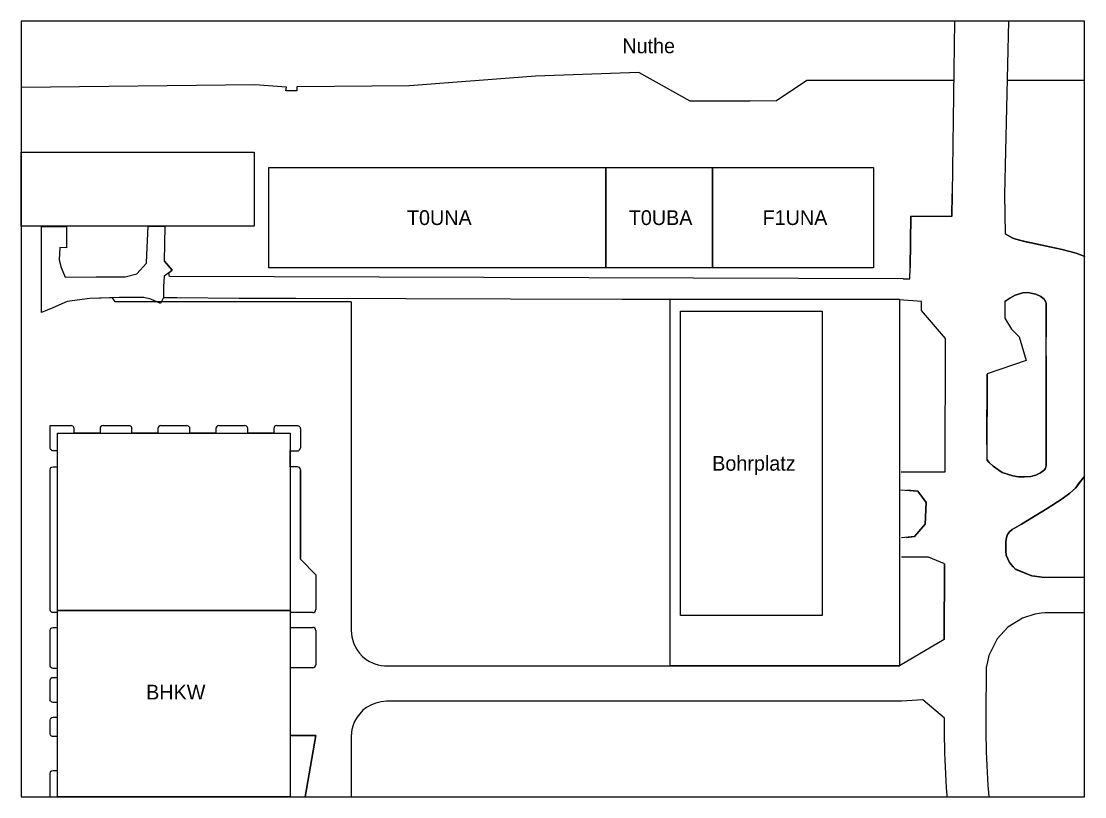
# Model space of a CAD drawing. Extents: x 0 to 0.18, y 0 to 0.131.
import ezdxf

# ---------------------------------------------------------------- set-up
doc = ezdxf.new("R2010")
doc.units = 0
doc.layers.add('ECN_KOPF_DE', color=7, linetype='Continuous')

msp = doc.modelspace()

# ---------------------------------------------------------------- linework, layer by layer
at = {"layer": 'ECN_KOPF_DE'}
for p, q in [((0.17999, 0.13127), (0, 0.13127)), ((0, 0.13127), (0, 0)), ((0.15796, 0.13127), (0.15756, 0.10208)), ((0.16711, 0.13127), (0.16643, 0.10192)), ((0.17999, 0), (0.17999, 0.13127)), ((0.10453, 0.12259), (0.08702, 0.122)), ((0.11323, 0.11773), (0.10453, 0.12259)), ((0.08702, 0.122), (0.06569, 0.12035)), ((0.13296, 0.12123), (0.12783, 0.11779)), ((0.15782, 0.12124), (0.13296, 0.12123)), ((0.17999, 0.12125), (0.16688, 0.12124)), ((0.03953, 0.12054), (0, 0.12008)), ((0.04489, 0.12013), (0.03953, 0.12054)), ((0.04476, 0.11949), (0.04489, 0.12013)), ((0.04666, 0.11947), (0.04476, 0.11949)), ((0.04667, 0.12015), (0.04666, 0.11947)), ((0.06569, 0.12035), (0.04667, 0.12015)), ((0.1234, 0.11777), (0.11323, 0.11773)), ((0.12783, 0.11779), (0.1234, 0.11777)), ((0, 0.10914), (0.03941, 0.10914)), ((0, 0.09658), (0, 0.10914)), ((0.03941, 0.10914), (0.03941, 0.09658)), ((0.04193, 0.10651), (0.09893, 0.10651)), ((0.04193, 0.08954), (0.04193, 0.10651)), ((0.09893, 0.10651), (0.09893, 0.08954)), ((0.09893, 0.10651), (0.11703, 0.10651)), ((0.09893, 0.08954), (0.09893, 0.10651)), ((0.11703, 0.10651), (0.11703, 0.08954)), ((0.11703, 0.10651), (0.14423, 0.10651)), ((0.11703, 0.08954), (0.11703, 0.10651)), ((0.14423, 0.10651), (0.14423, 0.08954)), ((0.15751, 0.0982), (0.15756, 0.10208)), ((0.15756, 0.10208), (0.15751, 0.0982)), ((0.16643, 0.10192), (0.16654, 0.09529)), ((0.16643, 0.10192), (0.16654, 0.09529)), ((0.15048, 0.08954), (0.15059, 0.09828)), ((0.15059, 0.09828), (0.15048, 0.08954)), ((0.15059, 0.09828), (0.15751, 0.0982)), ((0.15751, 0.0982), (0.15059, 0.09828)), ((0.03941, 0.09658), (0, 0.09658)), ((0.00342, 0.09654), (0.00763, 0.09655)), ((0.00342, 0.09654), (0.00763, 0.09655)), ((0.00342, 0.09296), (0.00342, 0.09654)), ((0.00342, 0.09296), (0.00342, 0.09654)), ((0.00763, 0.09655), (0.00764, 0.0929)), ((0.00763, 0.09655), (0.00764, 0.0929)), ((0.02127, 0.09172), (0.02147, 0.09656)), ((0.02127, 0.09172), (0.02147, 0.09656)), ((0.02147, 0.09656), (0.02438, 0.09656)), ((0.02147, 0.09656), (0.02438, 0.09656)), ((0.02422, 0.09064), (0.02438, 0.09658)), ((0.02422, 0.09064), (0.02438, 0.09658)), ((0.16654, 0.09529), (0.16782, 0.09455)), ((0.16782, 0.09455), (0.16654, 0.09529)), ((0.16782, 0.09455), (0.16835, 0.09437)), ((0.16835, 0.09437), (0.16782, 0.09455)), ((0.16835, 0.09437), (0.16984, 0.094)), ((0.16943, 0.09409), (0.16835, 0.09437)), ((0.17619, 0.09262), (0.16943, 0.09409)), ((0.16984, 0.094), (0.17619, 0.09262)), ((0.00342, 0.08895), (0.00342, 0.09296)), ((0.00342, 0.08895), (0.00342, 0.09296)), ((0.00653, 0.09296), (0.0064, 0.09087)), ((0.00653, 0.09296), (0.0064, 0.09087)), ((0.00764, 0.0929), (0.00653, 0.09296)), ((0.00764, 0.0929), (0.00653, 0.09296)), ((0.17619, 0.09262), (0.17857, 0.09203)), ((0.17857, 0.09203), (0.17619, 0.09262)), ((0.17857, 0.09203), (0.18001, 0.09148)), ((0.18001, 0.09148), (0.17857, 0.09203)), ((0.0064, 0.09087), (0.00676, 0.08958)), ((0.0064, 0.09087), (0.00676, 0.08958)), ((0.01954, 0.0885), (0.02121, 0.09031)), ((0.01954, 0.0885), (0.02121, 0.09031)), ((0.02121, 0.09031), (0.02127, 0.09172)), ((0.02121, 0.09031), (0.02127, 0.09172)), ((0.02553, 0.08916), (0.02422, 0.09064)), ((0.02422, 0.09064), (0.02553, 0.08916)), ((0.02553, 0.08916), (0.02422, 0.09064)), ((0.02422, 0.09064), (0.02553, 0.08916)), ((0.00343, 0.08383), (0.00342, 0.08895)), ((0.00343, 0.08383), (0.00342, 0.08895)), ((0.00676, 0.08958), (0.00744, 0.08796)), ((0.00676, 0.08958), (0.00744, 0.08796)), ((0.01758, 0.088), (0.01954, 0.0885)), ((0.01758, 0.088), (0.01954, 0.0885)), ((0.025, 0.0887), (0.02416, 0.08815)), ((0.025, 0.0887), (0.02416, 0.08815)), ((0.025, 0.0887), (0.02416, 0.08815)), ((0.025, 0.0887), (0.02553, 0.08916)), ((0.02553, 0.08916), (0.025, 0.0887)), ((0.025, 0.0887), (0.02553, 0.08916)), ((0.02553, 0.08916), (0.025, 0.0887)), ((0.0251, 0.08805), (0.025, 0.0887)), ((0.0251, 0.08805), (0.025, 0.0887)), ((0.0251, 0.08805), (0.025, 0.0887)), ((0.09893, 0.08954), (0.04193, 0.08954)), ((0.11703, 0.08954), (0.09893, 0.08954)), ((0.14423, 0.08954), (0.11703, 0.08954)), ((0.15043, 0.08765), (0.15048, 0.08954)), ((0.00744, 0.08796), (0.01265, 0.08799)), ((0.00744, 0.08796), (0.01265, 0.08799)), ((0.01265, 0.08799), (0.01758, 0.088)), ((0.01265, 0.08799), (0.01758, 0.088)), ((0.0241, 0.0864), (0.02408, 0.08452)), ((0.0241, 0.0864), (0.02408, 0.08452)), ((0.0241, 0.0864), (0.02408, 0.08452)), ((0.02416, 0.08815), (0.0241, 0.0864)), ((0.02416, 0.08815), (0.0241, 0.0864)), ((0.02416, 0.08815), (0.0241, 0.0864)), ((0.14928, 0.08767), (0.0251, 0.08805)), ((0.14928, 0.08767), (0.15043, 0.08765)), ((0.16824, 0.08489), (0.16734, 0.0844)), ((0.16734, 0.0844), (0.16824, 0.08489)), ((0.16951, 0.08531), (0.16824, 0.08489)), ((0.16824, 0.08489), (0.16882, 0.0851)), ((0.16882, 0.0851), (0.16951, 0.08531)), ((0.17037, 0.08536), (0.16951, 0.08531)), ((0.16951, 0.08531), (0.17037, 0.08536)), ((0.17171, 0.08507), (0.17037, 0.08536)), ((0.17037, 0.08536), (0.17171, 0.08507)), ((0.1726, 0.08467), (0.17171, 0.08507)), ((0.17171, 0.08507), (0.1726, 0.08467)), ((0.17318, 0.08416), (0.1726, 0.08467)), ((0.1726, 0.08467), (0.17318, 0.08416)), ((0.00342, 0.08198), (0.00343, 0.08383)), ((0.00342, 0.08198), (0.00343, 0.08383)), ((0.00777, 0.08382), (0.00532, 0.08279)), ((0.00777, 0.08382), (0.00532, 0.08279)), ((0.01162, 0.08433), (0.00777, 0.08382)), ((0.01162, 0.08433), (0.00777, 0.08382)), ((0.01162, 0.08433), (0.00777, 0.08382)), ((0.01656, 0.08449), (0.01162, 0.08433)), ((0.01656, 0.08449), (0.01162, 0.08433)), ((0.01542, 0.08445), (0.01162, 0.08433)), ((0.01592, 0.08377), (0.01542, 0.08445)), ((0.05534, 0.08377), (0.01592, 0.08377)), ((0.02077, 0.0845), (0.01656, 0.08449)), ((0.02077, 0.0845), (0.01656, 0.08449)), ((0.02191, 0.08422), (0.02077, 0.0845)), ((0.02191, 0.08422), (0.02077, 0.0845)), ((0.02355, 0.08348), (0.02191, 0.08422)), ((0.02355, 0.08348), (0.02191, 0.08422)), ((0.02408, 0.08452), (0.02355, 0.08348)), ((0.02408, 0.08452), (0.02355, 0.08348)), ((0.02408, 0.08452), (0.02633, 0.08449)), ((0.02633, 0.08449), (0.03689, 0.08442)), ((0.03689, 0.08442), (0.04649, 0.0844)), ((0.04649, 0.0844), (0.06511, 0.08434)), ((0.05584, 0.08377), (0.05534, 0.08377)), ((0.05584, 0.08377), (0.05584, 0.02815)), ((0.06511, 0.08434), (0.0828, 0.08429)), ((0.0828, 0.08429), (0.10173, 0.08423)), ((0.10173, 0.08423), (0.11909, 0.08421)), ((0.15236, 0.08383), (0.14865, 0.0841)), ((0.15237, 0.08232), (0.15236, 0.08383)), ((0.15237, 0.08232), (0.15236, 0.08383)), ((0.15236, 0.08383), (0.15236, 0.08383)), ((0.16649, 0.08382), (0.16648, 0.08102)), ((0.16649, 0.08382), (0.16648, 0.08102)), ((0.16734, 0.0844), (0.16649, 0.08382)), ((0.16649, 0.08382), (0.16734, 0.0844)), ((0.17349, 0.08357), (0.17318, 0.08416)), ((0.17318, 0.08416), (0.17349, 0.08357)), ((0.17348, 0.08005), (0.17349, 0.08357)), ((0.17349, 0.08357), (0.17348, 0.08005)), ((0.00532, 0.08279), (0.00342, 0.08198)), ((0.00532, 0.08279), (0.00342, 0.08198)), ((0.11156, 0.08221), (0.13556, 0.08221)), ((0.11156, 0.03068), (0.11156, 0.08221)), ((0.13556, 0.08221), (0.13556, 0.03068)), ((0.15642, 0.07757), (0.15237, 0.08232)), ((0.15642, 0.07757), (0.15237, 0.08232)), ((0.16648, 0.08102), (0.16764, 0.07914)), ((0.16648, 0.08102), (0.16764, 0.07914)), ((0.17348, 0.08005), (0.17344, 0.07556)), ((0.17346, 0.07387), (0.17348, 0.08005)), ((0.15636, 0.05502), (0.15642, 0.07757)), ((0.15636, 0.05502), (0.15642, 0.07757)), ((0.16764, 0.07914), (0.1689, 0.07783)), ((0.16764, 0.07914), (0.1689, 0.07783)), ((0.1689, 0.07783), (0.17011, 0.07386)), ((0.1689, 0.07783), (0.17011, 0.07386)), ((0.17011, 0.07386), (0.16348, 0.07158)), ((0.17011, 0.07386), (0.16349, 0.07158)), ((0.17344, 0.07556), (0.17346, 0.07387)), ((0.17348, 0.06465), (0.17346, 0.07387)), ((0.17346, 0.07387), (0.17348, 0.06465)), ((0.16348, 0.07158), (0.16342, 0.05711)), ((0.16343, 0.05965), (0.16348, 0.07156)), ((0.17348, 0.05605), (0.17348, 0.06465)), ((0.17348, 0.06465), (0.17348, 0.0577)), ((0.00489, 0.05905), (0.00489, 0.06284)), ((0.00489, 0.06284), (0.00844, 0.06282)), ((0.00614, 0.06157), (0.04554, 0.06157)), ((0.00614, 0.03152), (0.00614, 0.06157)), ((0.0087, 0.06275), (0.00844, 0.06282)), ((0.00884, 0.06261), (0.0087, 0.06275)), ((0.00891, 0.06248), (0.00884, 0.06261)), ((0.00894, 0.06232), (0.00891, 0.06248)), ((0.00894, 0.06157), (0.00894, 0.06232)), ((0.01334, 0.06157), (0.00894, 0.06157)), ((0.01338, 0.06252), (0.01334, 0.06232)), ((0.01334, 0.06232), (0.01334, 0.06157)), ((0.01348, 0.06267), (0.01338, 0.06252)), ((0.01363, 0.06277), (0.01348, 0.06267)), ((0.01384, 0.06282), (0.01363, 0.06277)), ((0.01384, 0.06282), (0.01824, 0.06282)), ((0.0185, 0.06275), (0.01824, 0.06282)), ((0.01864, 0.06261), (0.0185, 0.06275)), ((0.01871, 0.06248), (0.01864, 0.06261)), ((0.01874, 0.06232), (0.01871, 0.06248)), ((0.01874, 0.06157), (0.01874, 0.06232)), ((0.02314, 0.06157), (0.01874, 0.06157)), ((0.02318, 0.06252), (0.02314, 0.06232)), ((0.02314, 0.06232), (0.02314, 0.06157)), ((0.02328, 0.06267), (0.02318, 0.06252)), ((0.02343, 0.06277), (0.02328, 0.06267)), ((0.02364, 0.06282), (0.02343, 0.06277)), ((0.02364, 0.06282), (0.02804, 0.06282)), ((0.0283, 0.06275), (0.02804, 0.06282)), ((0.02844, 0.06261), (0.0283, 0.06275)), ((0.02851, 0.06248), (0.02844, 0.06261)), ((0.02854, 0.06232), (0.02851, 0.06248)), ((0.02854, 0.06157), (0.02854, 0.06232)), ((0.03294, 0.06157), (0.02854, 0.06157)), ((0.03298, 0.06252), (0.03294, 0.06232)), ((0.03294, 0.06232), (0.03294, 0.06157)), ((0.03308, 0.06267), (0.03298, 0.06252)), ((0.03323, 0.06277), (0.03308, 0.06267)), ((0.03344, 0.06282), (0.03323, 0.06277)), ((0.03344, 0.06282), (0.03784, 0.06282)), ((0.0381, 0.06275), (0.03784, 0.06282)), ((0.03824, 0.06261), (0.0381, 0.06275)), ((0.03831, 0.06248), (0.03824, 0.06261)), ((0.03834, 0.06232), (0.03831, 0.06248)), ((0.03834, 0.06157), (0.03834, 0.06232)), ((0.04274, 0.06157), (0.03834, 0.06157)), ((0.04278, 0.06252), (0.04274, 0.06232)), ((0.04274, 0.06232), (0.04274, 0.06157)), ((0.04288, 0.06267), (0.04278, 0.06252)), ((0.04303, 0.06277), (0.04288, 0.06267)), ((0.04324, 0.06282), (0.04303, 0.06277)), ((0.04324, 0.06282), (0.04676, 0.06282)), ((0.04554, 0.06157), (0.04554, 0.03152)), ((0.04674, 0.06282), (0.04679, 0.06281)), ((0.04679, 0.06281), (0.04685, 0.0628)), ((0.04685, 0.0628), (0.04693, 0.06278)), ((0.04693, 0.06278), (0.04702, 0.06273)), ((0.04702, 0.06273), (0.04709, 0.06267)), ((0.04709, 0.06267), (0.04716, 0.06259)), ((0.04716, 0.06259), (0.0472, 0.0625)), ((0.0472, 0.0625), (0.04723, 0.06242)), ((0.04723, 0.06242), (0.04724, 0.06232)), ((0.04724, 0.06232), (0.04724, 0.05905)), ((0.00496, 0.05879), (0.00489, 0.05905)), ((0.00509, 0.05865), (0.00496, 0.05879)), ((0.00522, 0.05858), (0.00509, 0.05865)), ((0.00539, 0.05855), (0.00522, 0.05858)), ((0.00614, 0.05855), (0.00539, 0.05855)), ((0.00614, 0.05585), (0.00614, 0.05855)), ((0.04554, 0.05585), (0.04554, 0.05855)), ((0.04554, 0.05855), (0.04674, 0.05855)), ((0.04674, 0.05855), (0.0469, 0.05858)), ((0.0469, 0.05858), (0.04703, 0.05865)), ((0.04703, 0.05865), (0.04717, 0.05879)), ((0.04717, 0.05879), (0.04724, 0.05905)), ((0.17348, 0.0577), (0.17348, 0.05605)), ((0.00503, 0.05571), (0.00518, 0.05581)), ((0.00518, 0.05581), (0.00539, 0.05585)), ((0.00539, 0.05585), (0.00614, 0.05585)), ((0.04674, 0.05585), (0.04554, 0.05585)), ((0.04694, 0.05581), (0.04674, 0.05585)), ((0.04709, 0.05571), (0.04694, 0.05581)), ((0.16342, 0.05711), (0.16382, 0.05658)), ((0.16382, 0.05658), (0.16346, 0.05705)), ((0.16382, 0.05658), (0.1645, 0.05597)), ((0.1645, 0.05597), (0.16382, 0.05658)), ((0.1645, 0.05597), (0.16604, 0.05491)), ((0.16529, 0.05538), (0.1645, 0.05597)), ((0.17337, 0.05561), (0.17348, 0.05605)), ((0.17348, 0.05605), (0.17337, 0.05561)), ((0.00489, 0.05535), (0.00493, 0.05556)), ((0.00489, 0.03167), (0.00489, 0.05535)), ((0.00493, 0.05556), (0.00503, 0.05571)), ((0.04719, 0.05556), (0.04709, 0.05571)), ((0.04724, 0.05535), (0.04719, 0.05556)), ((0.04724, 0.05535), (0.04724, 0.04035)), ((0.04724, 0.04022), (0.04724, 0.05522)), ((0.14896, 0.05498), (0.15636, 0.05502)), ((0.14987, 0.05499), (0.15636, 0.05502)), ((0.16604, 0.05491), (0.16529, 0.05538)), ((0.16604, 0.05491), (0.16784, 0.0543)), ((0.16676, 0.05464), (0.16604, 0.05491)), ((0.16784, 0.0543), (0.16676, 0.05464)), ((0.16784, 0.0543), (0.16878, 0.05418)), ((0.16878, 0.05418), (0.16784, 0.0543)), ((0.16878, 0.05418), (0.16982, 0.05414)), ((0.16982, 0.05414), (0.16878, 0.05418)), ((0.16982, 0.05414), (0.17086, 0.05423)), ((0.17086, 0.05423), (0.16982, 0.05414)), ((0.17086, 0.05423), (0.17174, 0.05446)), ((0.17174, 0.05446), (0.17086, 0.05423)), ((0.17174, 0.05446), (0.17252, 0.05481)), ((0.17252, 0.05481), (0.17174, 0.05446)), ((0.17252, 0.05481), (0.17322, 0.05535)), ((0.17322, 0.05535), (0.17252, 0.05481)), ((0.17322, 0.05535), (0.17337, 0.05561)), ((0.17337, 0.05561), (0.17322, 0.05535)), ((0.17984, 0.05411), (0.17842, 0.05226)), ((0.17915, 0.0532), (0.17984, 0.05411)), ((0.17999, 0.05432), (0.17984, 0.05411)), ((0.17984, 0.05411), (0.17999, 0.05432)), ((0.17842, 0.05226), (0.17749, 0.05141)), ((0.17749, 0.05141), (0.17842, 0.05226)), ((0.17842, 0.05226), (0.17915, 0.0532)), ((0.14888, 0.05196), (0.15178, 0.0517)), ((0.15178, 0.0517), (0.14987, 0.05187)), ((0.15318, 0.04981), (0.15178, 0.0517)), ((0.15178, 0.0517), (0.15318, 0.04981)), ((0.1762, 0.05045), (0.17367, 0.04878)), ((0.17367, 0.04878), (0.1762, 0.05045)), ((0.17749, 0.05141), (0.1762, 0.05045)), ((0.1762, 0.05045), (0.17749, 0.05141)), ((0.15299, 0.04612), (0.15318, 0.04981)), ((0.15318, 0.04981), (0.15299, 0.04612)), ((0.17367, 0.04878), (0.16928, 0.04616)), ((0.16928, 0.04616), (0.17367, 0.04878)), ((0.15118, 0.04403), (0.15299, 0.04612)), ((0.15299, 0.04612), (0.15118, 0.04403)), ((0.16773, 0.04523), (0.16729, 0.04484)), ((0.16729, 0.04484), (0.16773, 0.04523)), ((0.16928, 0.04616), (0.16773, 0.04523)), ((0.16773, 0.04523), (0.16928, 0.04616)), ((0.15118, 0.04403), (0.14899, 0.04381)), ((0.14986, 0.0439), (0.15118, 0.04403)), ((0.16674, 0.04391), (0.16663, 0.04314)), ((0.16663, 0.04314), (0.16674, 0.04391)), ((0.16693, 0.04439), (0.16674, 0.04391)), ((0.16674, 0.04391), (0.16693, 0.04439)), ((0.16729, 0.04484), (0.16693, 0.04439)), ((0.16693, 0.04439), (0.16729, 0.04484)), ((0.16663, 0.04314), (0.16667, 0.04156)), ((0.16667, 0.04156), (0.16663, 0.04314)), ((0.16667, 0.04156), (0.1667, 0.0409)), ((0.1667, 0.0409), (0.16667, 0.04156)), ((0.04984, 0.03756), (0.04724, 0.04022)), ((0.15012, 0.04056), (0.149, 0.04056)), ((0.15358, 0.04057), (0.14986, 0.04056)), ((0.15358, 0.04057), (0.15012, 0.04056)), ((0.15626, 0.0394), (0.15358, 0.04057)), ((0.15626, 0.0394), (0.15358, 0.04057)), ((0.1667, 0.0409), (0.1673, 0.03966)), ((0.1673, 0.03966), (0.1667, 0.0409)), ((0.1673, 0.03966), (0.16791, 0.03892)), ((0.16791, 0.03892), (0.1673, 0.03966)), ((0.15619, 0.02663), (0.15626, 0.0394)), ((0.15626, 0.0394), (0.15619, 0.02663)), ((0.16791, 0.03892), (0.16834, 0.03848)), ((0.16834, 0.03848), (0.16791, 0.03892)), ((0.17104, 0.03739), (0.16815, 0.03856)), ((0.16834, 0.03848), (0.17104, 0.03739)), ((0.04984, 0.03756), (0.04984, 0.03167)), ((0.17104, 0.03739), (0.17319, 0.03714)), ((0.17319, 0.03714), (0.17104, 0.03739)), ((0.17319, 0.03714), (0.17999, 0.03715)), ((0.17999, 0.03715), (0.17319, 0.03714)), ((0.00496, 0.03141), (0.00489, 0.03167)), ((0.00509, 0.03126), (0.00496, 0.03141)), ((0.00522, 0.0312), (0.00509, 0.03126)), ((0.00539, 0.03117), (0.00522, 0.0312)), ((0.00614, 0.03117), (0.00539, 0.03117)), ((0.04554, 0.03152), (0.00614, 0.03152)), ((0.00614, 0.03152), (0.04554, 0.03152)), ((0.00614, 0), (0.00614, 0.03152)), ((0.00614, 0.02866), (0.00614, 0.03117)), ((0.04554, 0.03152), (0.04554, 0)), ((0.04934, 0.03117), (0.04554, 0.03117)), ((0.04554, 0.03117), (0.04554, 0.02866)), ((0.13556, 0.03068), (0.11156, 0.03068)), ((0.17155, 0.03089), (0.16946, 0.03022)), ((0.17155, 0.03089), (0.16948, 0.03023)), ((0.17263, 0.03109), (0.17155, 0.03089)), ((0.17263, 0.03109), (0.17155, 0.03089)), ((0.17323, 0.03111), (0.17263, 0.03109)), ((0.17323, 0.03111), (0.17263, 0.03109)), ((0.17999, 0.03113), (0.17323, 0.03111)), ((0.17999, 0.03113), (0.17323, 0.03111)), ((0.16948, 0.03023), (0.16701, 0.02869)), ((0.16946, 0.03022), (0.16701, 0.02869)), ((0.00489, 0.02816), (0.00493, 0.02837)), ((0.00489, 0.02204), (0.00489, 0.02816)), ((0.00493, 0.02837), (0.00503, 0.02851)), ((0.00503, 0.02851), (0.00518, 0.02861)), ((0.00518, 0.02861), (0.00539, 0.02866)), ((0.00539, 0.02866), (0.00614, 0.02866)), ((0.04554, 0.02866), (0.04934, 0.02866)), ((0.04984, 0.02816), (0.04984, 0.02234)), ((0.05584, 0.02815), (0.05594, 0.02705)), ((0.05594, 0.02705), (0.05622, 0.02605)), ((0.16701, 0.02869), (0.16518, 0.02673)), ((0.16701, 0.02869), (0.16518, 0.02673)), ((0.05622, 0.02605), (0.05662, 0.0252)), ((0.15619, 0.02663), (0.14866, 0.02215)), ((0.16518, 0.02673), (0.16378, 0.0239)), ((0.16518, 0.02673), (0.16378, 0.0239)), ((0.05662, 0.0252), (0.05689, 0.02476)), ((0.05689, 0.02476), (0.05725, 0.02428)), ((0.05725, 0.02428), (0.05772, 0.02379)), ((0.05772, 0.02379), (0.05838, 0.02325)), ((0.16378, 0.0239), (0.16337, 0.02205)), ((0.16378, 0.0239), (0.16337, 0.02205)), ((0.00496, 0.02196), (0.00489, 0.02222)), ((0.00509, 0.02181), (0.00496, 0.02196)), ((0.00522, 0.02175), (0.00509, 0.02181)), ((0.00539, 0.02172), (0.00522, 0.02175)), ((0.00614, 0.02172), (0.00539, 0.02172)), ((0.00614, 0.02021), (0.00614, 0.02172)), ((0.04934, 0.02184), (0.04554, 0.02184)), ((0.04554, 0.02184), (0.04554, 0.01037)), ((0.05838, 0.02325), (0.05893, 0.02291)), ((0.05893, 0.02291), (0.05946, 0.02264)), ((0.05946, 0.02264), (0.05985, 0.02249)), ((0.05985, 0.02249), (0.0604, 0.02233)), ((0.0604, 0.02233), (0.06094, 0.02222)), ((0.06094, 0.02222), (0.06147, 0.02216)), ((0.06147, 0.02216), (0.06184, 0.02215)), ((0.06184, 0.02215), (0.14866, 0.02215)), ((0.16332, 0.01333), (0.16337, 0.02205)), ((0.00489, 0.01971), (0.00493, 0.01992)), ((0.00493, 0.01992), (0.00503, 0.02006)), ((0.00503, 0.02006), (0.00518, 0.02016)), ((0.00518, 0.02016), (0.00539, 0.02021)), ((0.00539, 0.02021), (0.00614, 0.02021)), ((0.00489, 0.01617), (0.00489, 0.01971)), ((0.00496, 0.01621), (0.00489, 0.01647)), ((0.00509, 0.01606), (0.00496, 0.01621)), ((0.15261, 0.01639), (0.14898, 0.01615)), ((0.15625, 0.01328), (0.15261, 0.01639)), ((0.00522, 0.016), (0.00509, 0.01606)), ((0.00539, 0.01597), (0.00522, 0.016)), ((0.00614, 0.01597), (0.00539, 0.01597)), ((0.00614, 0.01346), (0.00614, 0.01597)), ((0.05784, 0.01463), (0.05729, 0.01406)), ((0.05844, 0.0151), (0.05784, 0.01463)), ((0.05927, 0.01557), (0.05844, 0.0151)), ((0.05999, 0.01586), (0.05927, 0.01557)), ((0.0609, 0.01608), (0.05999, 0.01586)), ((0.06184, 0.01615), (0.0609, 0.01608)), ((0.14898, 0.01615), (0.06184, 0.01615)), ((0.00489, 0.01296), (0.00493, 0.01317)), ((0.00489, 0.01067), (0.00489, 0.01296)), ((0.00493, 0.01317), (0.00503, 0.01331)), ((0.00503, 0.01331), (0.00518, 0.01341)), ((0.00518, 0.01341), (0.00539, 0.01346)), ((0.00539, 0.01346), (0.00614, 0.01346)), ((0.05642, 0.01273), (0.05616, 0.01209)), ((0.05683, 0.01345), (0.05642, 0.01273)), ((0.05729, 0.01406), (0.05683, 0.01345)), ((0.15625, 0.0121), (0.15625, 0.01328)), ((0.16332, 0.01218), (0.16332, 0.01333)), ((0.05588, 0.01088), (0.05584, 0.01015)), ((0.05596, 0.01137), (0.05588, 0.01088)), ((0.05616, 0.01209), (0.05596, 0.01137)), ((0.15627, 0.01093), (0.15625, 0.0121)), ((0.15629, 0.00975), (0.15627, 0.01093)), ((0.16333, 0.01103), (0.16332, 0.01218)), ((0.16335, 0.00989), (0.16333, 0.01103)), ((0.00496, 0.01041), (0.00489, 0.01067)), ((0.00509, 0.01026), (0.00496, 0.01041)), ((0.00522, 0.0102), (0.00509, 0.01026)), ((0.00539, 0.01017), (0.00522, 0.0102)), ((0.00614, 0.01017), (0.00539, 0.01017)), ((0.00614, 0.00445), (0.00614, 0.01017)), ((0.04984, 0.01037), (0.04554, 0.01037)), ((0.04554, 0.01037), (0.04554, 0)), ((0.04554, 0.01037), (0.04984, 0.01037)), ((0.04984, 0.01037), (0.04806, 0)), ((0.04806, 0), (0.04984, 0.01037)), ((0.05584, 0.01052), (0.05584, 0)), ((0.15631, 0.00857), (0.15629, 0.00975)), ((0.16337, 0.00874), (0.16335, 0.00989)), ((0.15635, 0.00739), (0.15631, 0.00857)), ((0.15639, 0.00622), (0.15635, 0.00739)), ((0.1634, 0.0076), (0.16337, 0.00874)), ((0.16345, 0.00645), (0.1634, 0.0076)), ((0.15644, 0.00504), (0.15639, 0.00622)), ((0.16349, 0.00531), (0.16345, 0.00645)), ((0.00489, 0.00395), (0.00493, 0.00416)), ((0.00489, 0), (0.00489, 0.00395)), ((0.00493, 0.00416), (0.00503, 0.0043)), ((0.00503, 0.0043), (0.00518, 0.0044)), ((0.00518, 0.0044), (0.00539, 0.00445)), ((0.00539, 0.00445), (0.00614, 0.00445)), ((0.15649, 0.00387), (0.15644, 0.00504)), ((0.15656, 0.00269), (0.15649, 0.00387)), ((0.16355, 0.00416), (0.16349, 0.00531)), ((0.16361, 0.00302), (0.16355, 0.00416)), ((0.15663, 0.00151), (0.15656, 0.00269)), ((0.16368, 0.00188), (0.16361, 0.00302)), ((0.16376, 0.00073), (0.16368, 0.00188)), ((0, 0), (0.17999, 0)), ((0.04554, 0), (0.00614, 0)), ((0.15672, 0.00026), (0.15663, 0.00151)), ((0.15674, 0), (0.15672, 0.00026)), ((0.16381, 0), (0.16376, 0.00073))]:
    msp.add_line(p, q, dxfattribs=at)
msp.add_lwpolyline([(0.10986, 0.08422), (0.14866, 0.08422), (0.14866, 0.02215), (0.10986, 0.02215)], close=True, dxfattribs=at)
for centre, start, end in [((0.04934, 0.03167), 270, 360), ((0.04934, 0.02816), 0, 90), ((0.04934, 0.02234), 270, 360)]:
    msp.add_arc(centre, 0.0005, start, end, dxfattribs=at)

# ---------------------------------------------------------------- texts
for s, p in [('Nuthe', (0.10174, 0.12586)), ('T0UNA', (0.06528, 0.09678)), ('T0UBA', (0.10283, 0.09678)), ('F1UNA', (0.12548, 0.09678)), ('Bohrplatz', (0.11695, 0.05519)), ('BHKW', (0.02114, 0.01646))]:
    msp.add_text(s, height=0.0025, dxfattribs=at).set_placement(p)

doc.saveas('drawing.dxf')
